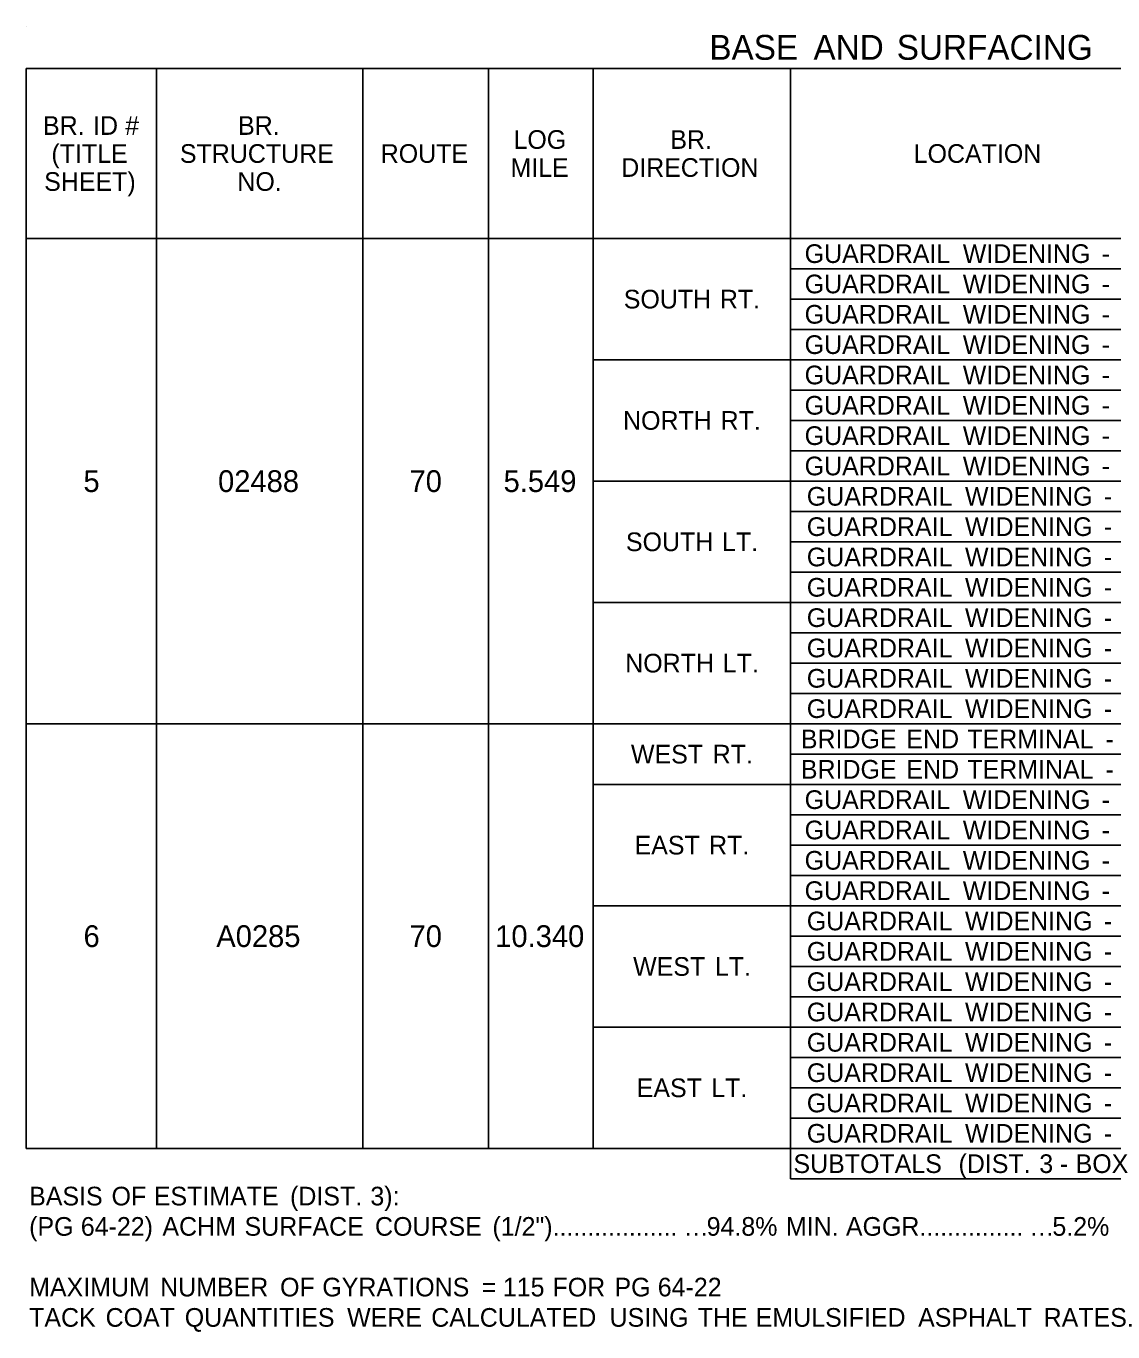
# Model space of a CAD drawing. Extents: x 544478 to 1930787, y -1948294 to 596640.
# Drawn here: x 552161.9 to 552511.3, y -1946674.2 to -1946254.5 of the extents above; entities that cross this region are included whole.
import ezdxf

# ---------------------------------------------------------------- set-up
doc = ezdxf.new("R2010")
doc.units = 0
doc.layers.add('Default', color=7, linetype='Continuous')

msp = doc.modelspace()

# ---------------------------------------------------------------- linework, layer by layer
at = {"layer": 'Default'}
for p, q in [((552161.91, -1946254.48), (552161.91, -1946254.48)), ((552161.91, -1946268.13), (552984.32, -1946268.13)), ((552161.91, -1946268.13), (552984.32, -1946268.13)), ((552161.91, -1946615.23), (552161.91, -1946268.13)), ((552203.83, -1946322.73), (552203.83, -1946268.13)), ((552270.13, -1946322.73), (552270.13, -1946268.13)), ((552310.59, -1946322.73), (552310.59, -1946268.13)), ((552344.23, -1946615.23), (552344.23, -1946268.13)), ((552407.61, -1946624.98), (552407.61, -1946268.13)), ((552161.91, -1946322.73), (552738.62, -1946322.73)), ((552203.83, -1946615.23), (552203.83, -1946322.73)), ((552270.13, -1946615.23), (552270.13, -1946322.73)), ((552310.59, -1946615.23), (552310.59, -1946322.73)), ((552407.61, -1946332.48), (552984.32, -1946332.48)), ((552407.61, -1946342.23), (552984.32, -1946342.23)), ((552407.61, -1946351.98), (552984.32, -1946351.98)), ((552344.23, -1946361.73), (552407.61, -1946361.73)), ((552407.61, -1946361.73), (552984.32, -1946361.73)), ((552407.61, -1946371.48), (552984.32, -1946371.48)), ((552407.61, -1946381.23), (552984.32, -1946381.23)), ((552407.61, -1946390.98), (552984.32, -1946390.98)), ((552344.23, -1946400.73), (552407.61, -1946400.73)), ((552407.61, -1946400.73), (552984.32, -1946400.73)), ((552407.61, -1946410.48), (552984.32, -1946410.48)), ((552407.61, -1946420.23), (552984.32, -1946420.23)), ((552407.61, -1946429.98), (552984.32, -1946429.98)), ((552344.23, -1946439.73), (552407.61, -1946439.73)), ((552407.61, -1946439.73), (552984.32, -1946439.73)), ((552407.61, -1946449.48), (552984.32, -1946449.48)), ((552407.61, -1946459.23), (552984.32, -1946459.23)), ((552407.61, -1946468.98), (552984.32, -1946468.98)), ((552161.91, -1946478.73), (552984.32, -1946478.73)), ((552407.61, -1946488.48), (552984.32, -1946488.48)), ((552344.23, -1946498.23), (552407.61, -1946498.23)), ((552407.61, -1946498.23), (552984.32, -1946498.23)), ((552407.61, -1946507.98), (552984.32, -1946507.98)), ((552407.61, -1946517.73), (552984.32, -1946517.73)), ((552407.61, -1946527.48), (552984.32, -1946527.48)), ((552344.23, -1946537.23), (552407.61, -1946537.23)), ((552407.61, -1946537.23), (552984.32, -1946537.23)), ((552407.61, -1946546.98), (552984.32, -1946546.98)), ((552407.61, -1946556.73), (552984.32, -1946556.73)), ((552407.61, -1946566.48), (552984.32, -1946566.48)), ((552344.23, -1946576.23), (552407.61, -1946576.23)), ((552407.61, -1946576.23), (552984.32, -1946576.23)), ((552407.61, -1946585.98), (552984.32, -1946585.98)), ((552407.61, -1946595.73), (552984.32, -1946595.73)), ((552407.61, -1946605.48), (552984.32, -1946605.48)), ((552161.91, -1946615.23), (552984.32, -1946615.23)), ((552407.61, -1946624.98), (552407.61, -1946615.23)), ((552407.61, -1946624.98), (552984.32, -1946624.98))]:
    msp.add_line(p, q, dxfattribs=at)

# ---------------------------------------------------------------- texts
for s, height, p in [('BASE', 8, (552381.54, -1946265.31)), (' AND', 8, (552412.05, -1946265.31)), (' SURFACING', 8, (552438.81, -1946265.31)), ('BR.', 6, (552167.34, -1946289.43)), (' ID', 6, (552181.21, -1946289.43)), (' #', 6, (552191.5, -1946289.43)), ('BR.', 6, (552230.05, -1946289.43)), ('LOG', 6, (552318.58, -1946293.93)), ('BR.', 6, (552368.99, -1946293.93)), ('(TITLE', 6, (552170.04, -1946298.43)), ('STRUCTURE', 6, (552211.34, -1946298.43)), ('ROUTE', 6, (552275.9, -1946298.43)), ('LOCATION', 6, (552447.23, -1946298.43)), ('MILE', 6, (552317.61, -1946302.93)), ('DIRECTION', 6, (552353.2, -1946302.93)), ('SHEET)', 6, (552167.71, -1946307.43)), ('NO.', 6, (552229.82, -1946307.43)), ('GUARDRAIL', 6, (552412.18, -1946330.61)), (' WIDENING', 6, (552460.79, -1946330.61)), (' -', 6, (552505.44, -1946330.61)), ('GUARDRAIL', 6, (552412.18, -1946340.36)), (' WIDENING', 6, (552460.79, -1946340.36)), ('SOUTH', 6, (552354.03, -1946345.23)), (' RT.', 6, (552382.7, -1946345.23)), (' -', 6, (552505.44, -1946340.36)), ('GUARDRAIL', 6, (552412.18, -1946350.11)), (' WIDENING', 6, (552460.79, -1946350.11)), (' -', 6, (552505.44, -1946350.11)), ('GUARDRAIL', 6, (552412.18, -1946359.86)), (' WIDENING', 6, (552460.79, -1946359.86)), (' -', 6, (552505.44, -1946359.86)), ('GUARDRAIL', 6, (552412.18, -1946369.61)), (' WIDENING', 6, (552460.79, -1946369.61)), (' -', 6, (552505.44, -1946369.61)), ('GUARDRAIL', 6, (552412.18, -1946379.36)), (' WIDENING', 6, (552460.79, -1946379.36)), ('NORTH', 6, (552353.8, -1946384.23)), (' RT.', 6, (552382.93, -1946384.23)), (' -', 6, (552505.44, -1946379.36)), ('GUARDRAIL', 6, (552412.18, -1946389.11)), (' WIDENING', 6, (552460.79, -1946389.11)), (' -', 6, (552505.44, -1946389.11)), ('GUARDRAIL', 6, (552412.18, -1946398.86)), (' WIDENING', 6, (552460.79, -1946398.86)), ('5', 7, (552180.34, -1946404.23)), ('02488', 7, (552223.61, -1946404.23)), ('70', 7, (552285.16, -1946404.23)), ('5.549', 7, (552315.4, -1946404.23)), (' -', 6, (552505.44, -1946398.86)), ('GUARDRAIL', 6, (552412.87, -1946408.61)), (' WIDENING', 6, (552461.49, -1946408.61)), (' -', 6, (552506.14, -1946408.61)), ('GUARDRAIL', 6, (552412.87, -1946418.36)), (' WIDENING', 6, (552461.49, -1946418.36)), (' -', 6, (552506.14, -1946418.36)), ('SOUTH', 6, (552354.73, -1946423.23)), (' LT.', 6, (552383.4, -1946423.23)), ('GUARDRAIL', 6, (552412.87, -1946428.11)), (' WIDENING', 6, (552461.49, -1946428.11)), (' -', 6, (552506.14, -1946428.11)), ('GUARDRAIL', 6, (552412.87, -1946437.86)), (' WIDENING', 6, (552461.49, -1946437.86)), (' -', 6, (552506.14, -1946437.86)), ('GUARDRAIL', 6, (552412.87, -1946447.61)), (' WIDENING', 6, (552461.49, -1946447.61)), (' -', 6, (552506.14, -1946447.61)), ('GUARDRAIL', 6, (552412.87, -1946457.36)), (' WIDENING', 6, (552461.49, -1946457.36)), ('NORTH', 6, (552354.5, -1946462.23)), (' LT.', 6, (552383.63, -1946462.23)), (' -', 6, (552506.14, -1946457.36)), ('GUARDRAIL', 6, (552412.87, -1946467.11)), (' WIDENING', 6, (552461.49, -1946467.11)), (' -', 6, (552506.14, -1946467.11)), ('GUARDRAIL', 6, (552412.87, -1946476.86)), (' WIDENING', 6, (552461.49, -1946476.86)), (' -', 6, (552506.14, -1946476.86)), ('BRIDGE', 6, (552410.96, -1946486.61)), (' END', 6, (552442.66, -1946486.61)), (' TERMINAL', 6, (552462.24, -1946486.61)), ('WEST', 6, (552356.34, -1946491.48)), (' RT.', 6, (552380.39, -1946491.48)), (' -', 6, (552506.66, -1946486.61)), ('BRIDGE', 6, (552410.96, -1946496.36)), (' END', 6, (552442.66, -1946496.36)), (' TERMINAL', 6, (552462.24, -1946496.36)), (' -', 6, (552506.66, -1946496.36)), ('GUARDRAIL', 6, (552412.18, -1946506.11)), (' WIDENING', 6, (552460.79, -1946506.11)), (' -', 6, (552505.44, -1946506.11)), ('GUARDRAIL', 6, (552412.18, -1946515.86)), (' WIDENING', 6, (552460.79, -1946515.86)), ('EAST', 6, (552357.5, -1946520.73)), (' RT.', 6, (552379.23, -1946520.73)), (' -', 6, (552505.44, -1946515.86)), ('GUARDRAIL', 6, (552412.18, -1946525.61)), (' WIDENING', 6, (552460.79, -1946525.61)), (' -', 6, (552505.44, -1946525.61)), ('GUARDRAIL', 6, (552412.18, -1946535.36)), (' WIDENING', 6, (552460.79, -1946535.36)), (' -', 6, (552505.44, -1946535.36)), ('GUARDRAIL', 6, (552412.87, -1946545.11)), (' WIDENING', 6, (552461.49, -1946545.11)), ('6', 7, (552180.37, -1946550.48)), ('A0285', 7, (552223.04, -1946550.48)), ('70', 7, (552285.16, -1946550.48)), ('10.340', 7, (552312.7, -1946550.48)), (' -', 6, (552506.14, -1946545.11)), ('GUARDRAIL', 6, (552412.87, -1946554.86)), (' WIDENING', 6, (552461.49, -1946554.86)), ('WEST', 6, (552357.04, -1946559.73)), (' LT.', 6, (552381.09, -1946559.73)), (' -', 6, (552506.14, -1946554.86)), ('GUARDRAIL', 6, (552412.87, -1946564.61)), (' WIDENING', 6, (552461.49, -1946564.61)), (' -', 6, (552506.14, -1946564.61)), ('GUARDRAIL', 6, (552412.87, -1946574.36)), (' WIDENING', 6, (552461.49, -1946574.36)), (' -', 6, (552506.14, -1946574.36)), ('GUARDRAIL', 6, (552412.87, -1946584.11)), (' WIDENING', 6, (552461.49, -1946584.11)), (' -', 6, (552506.14, -1946584.11)), ('GUARDRAIL', 6, (552412.87, -1946593.86)), (' WIDENING', 6, (552461.49, -1946593.86)), ('EAST', 6, (552358.2, -1946598.73)), (' LT.', 6, (552379.93, -1946598.73)), (' -', 6, (552506.14, -1946593.86)), ('GUARDRAIL', 6, (552412.87, -1946603.61)), (' WIDENING', 6, (552461.49, -1946603.61)), (' -', 6, (552506.14, -1946603.61)), ('GUARDRAIL', 6, (552412.87, -1946613.36)), (' WIDENING', 6, (552461.49, -1946613.36)), (' -', 6, (552506.14, -1946613.36)), ('SUBTOTALS', 6, (552408.58, -1946623.11)), (' (DIST.', 6, (552459.41, -1946623.11)), (' 3', 6, (552485.37, -1946623.11)), (' BOX', 6, (552497.06, -1946623.11)), (' -', 6, (552492, -1946623.11)), ('BASIS', 6, (552162.88, -1946633.53)), (' OF', 6, (552187.14, -1946633.53)), (' ESTIMATE', 6, (552200.73, -1946633.53)), (' (DIST.', 6, (552244.53, -1946633.53)), (' 3):', 6, (552270.35, -1946633.53)), ('(PG', 6, (552162.88, -1946643.28)), (' 64-22)', 6, (552177.26, -1946643.28)), (' ACHM', 6, (552203.5, -1946643.28)), (' SURFACE', 6, (552229.89, -1946643.28)), (' COURSE', 6, (552271.83, -1946643.28)), (' (1/2")..................', 6, (552309.58, -1946643.28)), ('94.8%', 6, (552380.68, -1946643.28)), (' MIN.', 6, (552403.92, -1946643.28)), (' AGGR...............', 6, (552423.21, -1946643.28)), ('5.2%', 6, (552491.82, -1946643.28)), ('…', 6, (552373.28, -1946643.28)), ('…', 6, (552484.42, -1946643.28)), ('MAXIMUM', 6, (552162.88, -1946662.78)), (' NUMBER', 6, (552202.77, -1946662.78)), (' OF', 6, (552241.32, -1946662.78)), (' GYRATIONS', 6, (552254.9, -1946662.78)), (' =', 6, (552306.17, -1946662.78)), (' 115', 6, (552312.93, -1946662.78)), (' FOR', 6, (552328.9, -1946662.78)), (' PG', 6, (552348.81, -1946662.78)), (' 64-22', 6, (552362.73, -1946662.78)), ('TACK', 6, (552162.88, -1946672.53)), (' COAT', 6, (552185.23, -1946672.53)), (' QUANTITIES', 6, (552210.68, -1946672.53)), (' WERE', 6, (552262.87, -1946672.53)), (' CALCULATED', 6, (552289.91, -1946672.53)), (' USING', 6, (552347.23, -1946672.53)), (' THE', 6, (552375.58, -1946672.53)), (' EMULSIFIED', 6, (552394.23, -1946672.53)), (' ASPHALT', 6, (552446.42, -1946672.53)), (' RATES.', 6, (552486.78, -1946672.53))]:
    msp.add_text(s, height=height, dxfattribs=at).set_placement(p)

doc.saveas('drawing.dxf')
